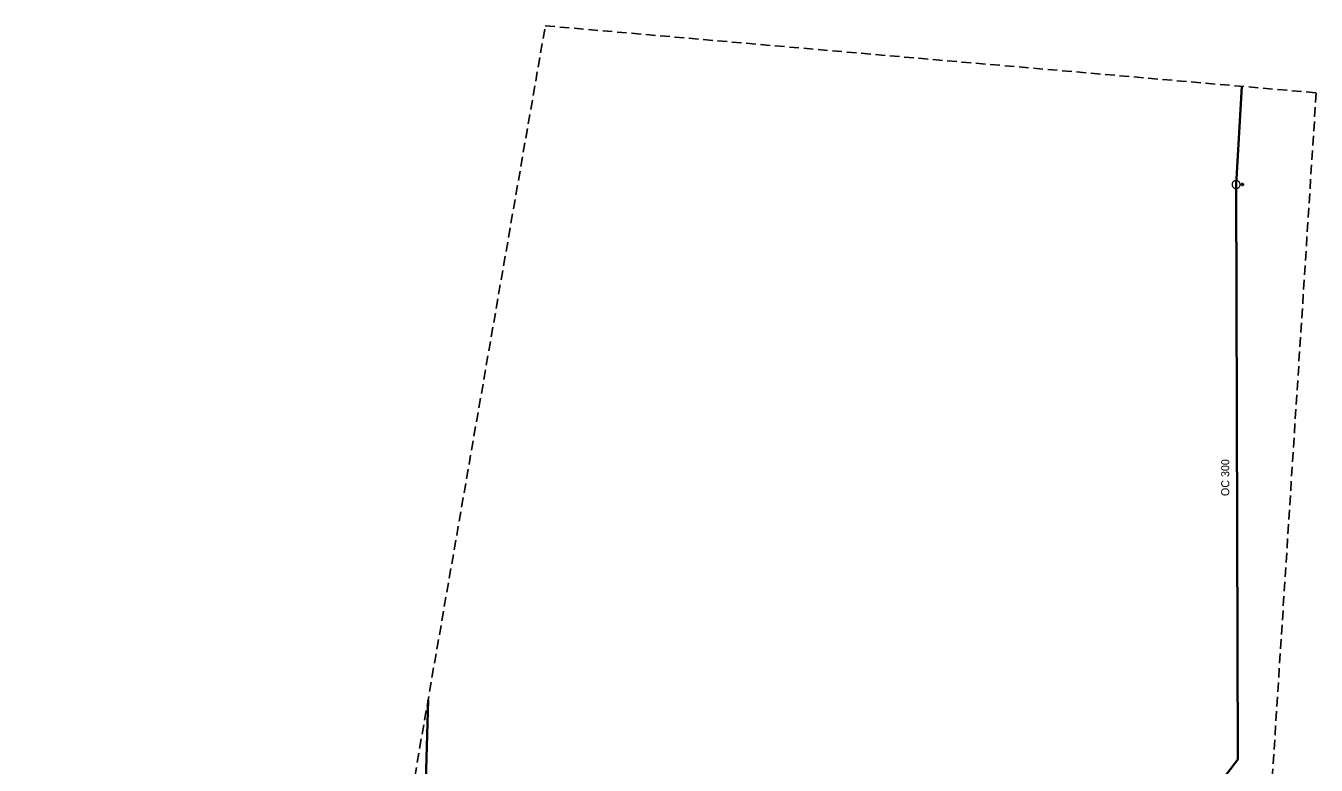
# Model space of a CAD drawing. Extents: x -724358 to -723714, y -973310 to -972026.
# Drawn here: x -723874.8 to -723713.6, y -972118.7 to -972026.3 of the extents above; entities that cross this region are included whole.
import ezdxf

# ---------------------------------------------------------------- set-up
doc = ezdxf.new("R2010")
doc.units = 0
doc.header["$LTSCALE"] = 0.4
doc.linetypes.add('MEDIUM_DASHED', pattern=[4.5, 3, -1.5])
for name, color, linetype, lineweight in [('1', 7, 'Continuous', 13), ('11', 7, 'Continuous', 13), ('17', 7, 'Continuous', 25), ('23', 7, 'Continuous', 13)]:
    doc.layers.add(name, color=color, linetype=linetype, lineweight=lineweight)

msp = doc.modelspace()

# ---------------------------------------------------------------- linework, layer by layer
at = {"layer": '1', "linetype": 'MEDIUM_DASHED', "lineweight": 25}
msp.add_lwpolyline([(-723809.944, -972026.35), (-723713.647, -972034.723), (-723734.581, -972361.295), (-724123.956, -973039.561), (-724241.187, -973309.611), (-724358.418, -973148.418), (-723860.186, -972315.24)], close=True, dxfattribs=at)
at = {"layer": '11', "lineweight": 35}
msp.add_lwpolyline([(-723742.539, -972182.375), (-723743.653, -972215.278), (-723756.353, -972217.294), (-723762.745, -972244.802), (-723778.784, -972244.465), (-723826.592, -972242.306), (-723825.083, -972127.91), (-723824.595, -972110.591)], dxfattribs=at)
at = {"layer": '17', "lineweight": 35}
msp.add_lwpolyline([(-723743.773, -972188.606), (-723742.971, -972179.993), (-723740.07, -972139.669), (-723723.419, -972117.993), (-723723.649, -972046.19), (-723722.935, -972033.916)], dxfattribs=at)
at = {"layer": '23'}
for p, q in [((-723722.692, -972046.18), (-723723.157, -972046.182)), ((-723722.94, -972046.017), (-723722.94, -972046.182)), ((-723722.938, -972046.347), (-723722.692, -972046.18)), ((-723722.917, -972046.031), (-723722.916, -972046.331)), ((-723722.889, -972046.048), (-723722.888, -972046.315)), ((-723722.866, -972046.066), (-723722.864, -972046.294)), ((-723722.843, -972046.083), (-723722.84, -972046.279)), ((-723722.818, -972046.098), (-723722.816, -972046.264)), ((-723722.791, -972046.114), (-723722.79, -972046.248)), ((-723722.767, -972046.13), (-723722.765, -972046.231)), ((-723722.743, -972046.149), (-723722.742, -972046.213)), ((-723722.716, -972046.164), (-723722.715, -972046.196))]:
    msp.add_line(p, q, dxfattribs=at)
msp.add_lwpolyline([(-723723.645, -972046.69), (-723723.593, -972046.686), (-723723.542, -972046.679), (-723723.491, -972046.665), (-723723.442, -972046.646), (-723723.395, -972046.622), (-723723.352, -972046.592), (-723723.312, -972046.559), (-723723.274, -972046.522), (-723723.242, -972046.482), (-723723.214, -972046.438), (-723723.19, -972046.391), (-723723.173, -972046.34), (-723723.158, -972046.291), (-723723.15, -972046.238), (-723723.149, -972046.186), (-723723.153, -972046.135), (-723723.16, -972046.083), (-723723.174, -972046.032), (-723723.192, -972045.985), (-723723.216, -972045.938), (-723723.246, -972045.894), (-723723.279, -972045.853), (-723723.317, -972045.815), (-723723.357, -972045.784), (-723723.401, -972045.755), (-723723.448, -972045.731), (-723723.497, -972045.714), (-723723.547, -972045.701), (-723723.599, -972045.693), (-723723.652, -972045.69), (-723723.703, -972045.694), (-723723.755, -972045.701), (-723723.806, -972045.715), (-723723.854, -972045.734), (-723723.901, -972045.759), (-723723.945, -972045.787), (-723723.986, -972045.82), (-723724.022, -972045.857), (-723724.054, -972045.898), (-723724.083, -972045.942), (-723724.107, -972045.989), (-723724.125, -972046.038), (-723724.138, -972046.09), (-723724.146, -972046.142), (-723724.148, -972046.194), (-723724.144, -972046.246), (-723724.136, -972046.297), (-723724.123, -972046.348), (-723724.105, -972046.396), (-723724.08, -972046.443), (-723724.052, -972046.486), (-723724.018, -972046.525), (-723723.981, -972046.562), (-723723.94, -972046.597), (-723723.896, -972046.625), (-723723.849, -972046.649), (-723723.8, -972046.666), (-723723.749, -972046.679), (-723723.697, -972046.688)], close=True, dxfattribs=at)
msp.add_lwpolyline([(-723722.692, -972046.18), (-723722.94, -972046.017), (-723722.938, -972046.347)], dxfattribs=at)

# ---------------------------------------------------------------- texts
at = {"layer": '1'}
msp.add_text('OC 300', height=1, rotation=90, dxfattribs=at).set_placement((-723724.509, -972085.094))

doc.saveas('drawing.dxf')
